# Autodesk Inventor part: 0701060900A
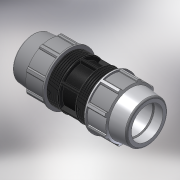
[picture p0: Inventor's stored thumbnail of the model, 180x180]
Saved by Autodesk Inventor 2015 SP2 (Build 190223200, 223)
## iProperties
Created: 2017-02
Part Number: 0701060900A
Material: Generic
Description: PLASSON COUPLER 90-90
Document SubType Name: Modeling
Designer: KIM
Mass: 3885.53 g
Surface Area: 4713.66 cm^2
Volume: 3885.53 cm^3
Density: 1 g/cm^3
Appearance: Default
Author: KIM
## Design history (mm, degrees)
derived "87010.ipt"
feature "Solid1::87010.ipt"
tag "TaggingFeature1"
body "Solid1"
other parameters: "d1" = 335, "d4" = 27.91667, "d5" = 47.85714, "d7" = 154, "d8" = 115.5, "d9" = 47.85714, "d11" = 4.78571, "d12" = 123.2, "d13" = 120 deg, "d14" = 117, "d15" = 6 deg, "d16" = 138.6, "d18" = 4.5, "d19" = 35 deg, "d20" = 17.5 deg, "d21" = 143.22, "d23" = 0, "d25" = 360 deg, "d27" = 3.08, "d33" = 1.8, "d34" = 7.7, "d36" = 0, "d37" = 1.8, "d38" = 1.8, "d40" = 360 deg, "d42" = 60.3, "d46" = 2.7, "d50" = 4.1875, "d51" = 0, "d53" = 3.06286, "d54" = 3.06286, "d57" = 6.12571, "d62" = 135.828, "d64" = 81, "d65" = 165, "E_" = 154, "H_" = 335, "l_" = 165, "d52" = 30.62857
